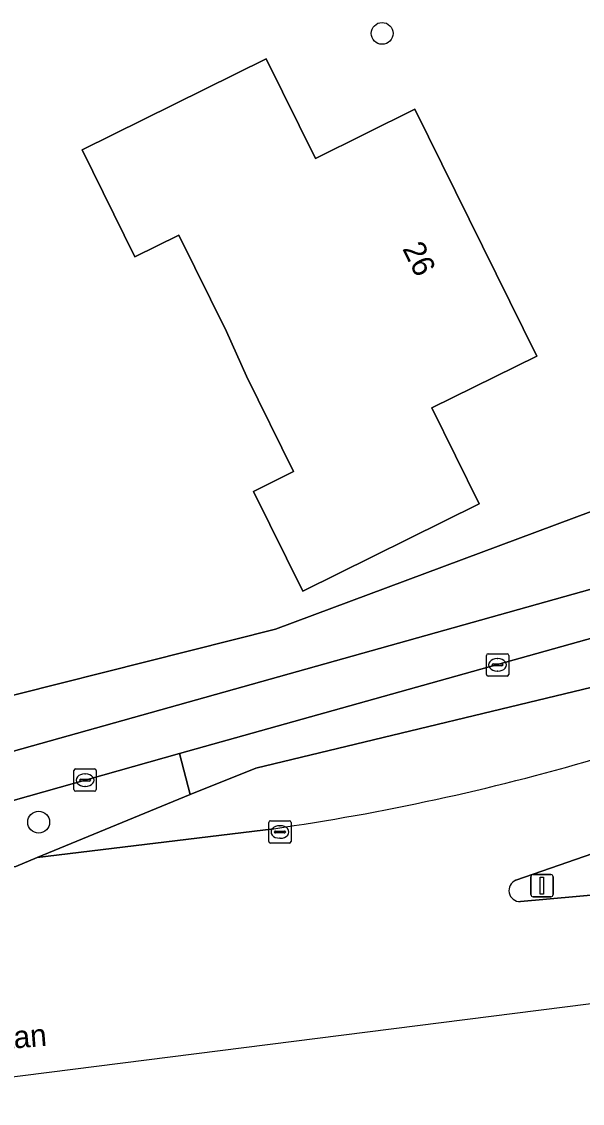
# Model space of a CAD drawing. Extents: x 161087 to 161926, y 382572 to 383873.
# Drawn here: x 161738.69 to 161763.81, y 382571.87 to 382620.31 of the extents above; entities that cross this region are included whole.
import ezdxf

# ---------------------------------------------------------------- set-up
doc = ezdxf.new("R2010")
doc.units = 0
for name, color, linetype in [('IMGEO_Boom', 7, 'Continuous'), ('IMGEO_Erf', 7, 'Continuous'), ('IMGEO_Fietspad_open', 7, 'Continuous'), ('IMGEO_Kolk', 7, 'Continuous'), ('IMGEO_Lichtmast', 7, 'Continuous'), ('IMGEO_Openbare_ruimte_label', 7, 'Continuous'), ('IMGEO_Pand', 7, 'Continuous'), ('IMGEO_Pand_nummerreeks', 7, 'Continuous'), ('IMGEO_Rijbaan_lokaal_gesloten', 7, 'Continuous'), ('IMGEO_Rioolput', 7, 'Continuous'), ('IMGEO_Verkeerseiland_groen', 7, 'Continuous'), ('IMGEO_Verkeerseiland_open', 7, 'Continuous'), ('IMGEO_Voetpad_open', 7, 'Continuous')]:
    doc.layers.add(name, color=color, linetype=linetype)

msp = doc.modelspace()

# ---------------------------------------------------------------- linework, layer by layer
at = {"layer": 'IMGEO_Boom'}
for centre in [(161754.841, 382619.783), (161739.452, 382584.466)]:
    msp.add_circle(centre, 0.489, dxfattribs=at)
at = {"layer": 'IMGEO_Erf'}
msp.add_lwpolyline([(161741.395, 382614.568), (161749.649, 382618.648), (161751.856, 382614.185), (161756.305, 382616.384), (161761.767, 382605.333), (161757.071, 382603.011), (161759.192, 382598.72), (161751.281, 382594.809), (161749.074, 382599.273), (161750.875, 382600.162), (161748.761, 382604.439), (161747.87, 382606.439), (161745.738, 382610.752), (161743.764, 382609.776)], close=True, dxfattribs=at)
msp.add_lwpolyline([(161728.057, 382587.75), (161732.732, 382588.753), (161750.068, 382593.111), (161776.833, 382603.073)], dxfattribs=at)
at = {"layer": 'IMGEO_Fietspad_open'}
for points in [[(161776.981, 382598.483), (161731.713, 382585.795)], [(161727.79, 382582.818), (161733.632, 382584.112), (161735.548, 382584.657), (161745.758, 382587.539), (161767.27, 382593.561), (161777.834, 382596.519), (161780.697, 382597.213), (161780.8, 382597.237), (161780.904, 382597.262)]]:
    msp.add_lwpolyline(points, dxfattribs=at)
at = {"layer": 'IMGEO_Kolk'}
for p, q in [((161741.033, 382585.922), (161741.033, 382586.774)), ((161741.108, 382586.848), (161741.96, 382586.848)), ((161741.521, 382586.628), (161741.546, 382586.628)), ((161742.034, 382586.774), (161742.034, 382585.922)), ((161741.292, 382586.342), (161741.292, 382586.354)), ((161741.73, 382586.305), (161741.332, 382586.305)), ((161741.335, 382586.391), (161741.733, 382586.391)), ((161741.776, 382586.354), (161741.776, 382586.342)), ((161741.96, 382585.848), (161741.108, 382585.848)), ((161741.544, 382586.068), (161741.519, 382586.068)), ((161749.762, 382583.6), (161749.762, 382584.452)), ((161749.837, 382584.526), (161750.689, 382584.526)), ((161750.25, 382584.306), (161750.275, 382584.306)), ((161750.763, 382584.452), (161750.763, 382583.6)), ((161750.021, 382584.02), (161750.021, 382584.032)), ((161750.459, 382583.983), (161750.061, 382583.983)), ((161750.064, 382584.069), (161750.462, 382584.069)), ((161750.273, 382583.746), (161750.248, 382583.746)), ((161750.505, 382584.032), (161750.505, 382584.02)), ((161750.689, 382583.526), (161749.837, 382583.526))]:
    msp.add_line(p, q, dxfattribs=at)
for points in [[(161741.033, 382585.922), (161741.033, 382586.774)], [(161741.108, 382586.848), (161741.96, 382586.848)], [(161742.034, 382586.774), (161742.034, 382585.922)], [(161741.96, 382585.848), (161741.108, 382585.848)], [(161749.762, 382583.6), (161749.762, 382584.452)], [(161749.837, 382584.526), (161750.689, 382584.526)], [(161750.763, 382584.452), (161750.763, 382583.6)], [(161750.689, 382583.526), (161749.837, 382583.526)]]:
    msp.add_lwpolyline(points, dxfattribs=at)
for centre, radius, start, end in [((161741.11, 382586.772), 0.0765, 91.552, 178.448), ((161741.11, 382586.772), 0.0765, 91.552, 178.448), ((161741.958, 382586.772), 0.0765, 1.552, 88.448), ((161741.958, 382586.772), 0.0765, 1.552, 88.448), ((161741.332, 382586.351), 0.0403, 85.8775, 175.7526), ((161741.329, 382586.341), 0.0366, 178.938, 274.7102), ((161741.733, 382586.348), 0.043, 264.8664, 352.4533), ((161741.737, 382586.353), 0.0386, 1.7309, 96.639), ((161741.11, 382585.924), 0.0765, 181.552, 268.448), ((161741.11, 382585.924), 0.0765, 181.552, 268.448), ((161741.958, 382585.924), 0.0765, 271.552, 358.448), ((161741.958, 382585.924), 0.0765, 271.552, 358.448), ((161749.839, 382584.45), 0.0765, 91.552, 178.448), ((161749.839, 382584.45), 0.0765, 91.552, 178.448), ((161750.687, 382584.45), 0.0765, 1.552, 88.448), ((161750.687, 382584.45), 0.0765, 1.552, 88.448), ((161750.061, 382584.029), 0.0403, 85.8775, 175.7526), ((161750.058, 382584.019), 0.0366, 178.938, 274.7102), ((161750.462, 382584.026), 0.043, 264.8664, 352.4533), ((161750.466, 382584.031), 0.0386, 1.7309, 96.639), ((161749.839, 382583.602), 0.0765, 181.552, 268.448), ((161749.839, 382583.602), 0.0765, 181.552, 268.448), ((161750.687, 382583.602), 0.0765, 271.552, 358.448), ((161750.687, 382583.602), 0.0765, 271.552, 358.448)]:
    msp.add_arc(centre, radius, start, end, dxfattribs=at)
for centre, major_axis, ratio, start_param, end_param in [((161741.52, 382586.348), (-0.387, 0.002), 0.722429, 4.712389, 7.853982), ((161741.545, 382586.348), (-0.39, 0.002), 0.717154, 1.570796, 4.712389), ((161750.249, 382584.026), (-0.387, 0.002), 0.722429, 4.712389, 7.853982), ((161750.274, 382584.026), (-0.39, 0.002), 0.717154, 1.570796, 4.712389)]:
    msp.add_ellipse(centre, major_axis=major_axis, ratio=ratio, start_param=start_param, end_param=end_param, dxfattribs=at)
at = {"layer": 'IMGEO_Lichtmast'}
for p, q in [((161761.508, 382581.222), (161761.508, 382582.022)), ((161761.508, 382582.022), (161761.508, 382581.222)), ((161761.608, 382582.122), (161762.398, 382582.122)), ((161762.398, 382582.122), (161761.608, 382582.122)), ((161762.498, 382582.022), (161762.498, 382581.222)), ((161762.498, 382581.222), (161762.498, 382582.022)), ((161762.398, 382581.122), (161761.608, 382581.122)), ((161761.608, 382581.122), (161762.398, 382581.122))]:
    msp.add_line(p, q, dxfattribs=at)
msp.add_lwpolyline([(161761.928, 382581.997), (161762.078, 382581.997), (161762.078, 382581.247), (161761.928, 382581.247), (161761.928, 382581.997)], dxfattribs=at)
for centre, start, end in [((161761.608, 382582.022), 90, 180), ((161761.608, 382582.022), 90, 180), ((161762.398, 382582.022), 0, 90), ((161762.398, 382582.022), 360, 90), ((161761.608, 382581.222), 180, 270), ((161761.608, 382581.222), 180, 270), ((161762.398, 382581.222), 270, 0), ((161762.398, 382581.222), 270, 0)]:
    msp.add_arc(centre, 0.1, start, end, dxfattribs=at)
at = {"layer": 'IMGEO_Pand'}
msp.add_lwpolyline([(161751.281, 382594.809), (161759.192, 382598.72), (161757.071, 382603.011), (161761.767, 382605.333), (161756.305, 382616.384), (161751.856, 382614.185), (161749.649, 382618.648), (161741.395, 382614.568), (161743.764, 382609.776), (161745.738, 382610.752), (161747.87, 382606.439), (161748.761, 382604.439), (161750.875, 382600.162), (161749.074, 382599.273)], close=True, dxfattribs=at)
at = {"layer": 'IMGEO_Rijbaan_lokaal_gesloten'}
for points in [[(161563.602, 382736.77), (161592.087, 382705.487), (161622.627, 382671.947), (161661.586, 382630.771), (161701.238, 382588.176), (161728.827, 382571.874), (161779.525, 382578.285), (161779.123, 382582.55), (161766.2, 382581.371), (161761.033, 382580.909)], [(161777.209, 382591.493), (161766.67, 382591.087), (161749.183, 382586.884), (161746.238, 382585.697), (161739.389, 382582.883), (161749.988, 382584.173)], [(161760.828, 382581.863), (161765.444, 382583.47), (161771.281, 382585.403)], [(161749.988, 382584.173), (161739.389, 382582.883), (161738.423, 382582.476), (161734.508, 382581.982)]]:
    msp.add_lwpolyline(points, dxfattribs=at)
for centre, radius, start, end in [((161735.059, 382687.795), 104.692, 278.19805, 286.26639), ((161735.059, 382687.795), 104.692, 278.19805, 286.26639), ((161761.017, 382581.405), 0.496, 112.3641, 271.8911)]:
    msp.add_arc(centre, radius, start, end, dxfattribs=at)
at = {"layer": 'IMGEO_Rioolput'}
for p, q in [((161759.585, 382592.007), (161760.437, 382592.007)), ((161759.51, 382591.081), (161759.51, 382591.933)), ((161759.769, 382591.501), (161759.769, 382591.513)), ((161759.812, 382591.55), (161760.21, 382591.55)), ((161759.998, 382591.787), (161760.023, 382591.787)), ((161760.253, 382591.513), (161760.253, 382591.501)), ((161760.511, 382591.933), (161760.511, 382591.081)), ((161760.437, 382591.007), (161759.585, 382591.007)), ((161760.207, 382591.464), (161759.809, 382591.464)), ((161760.021, 382591.227), (161759.996, 382591.227))]:
    msp.add_line(p, q, dxfattribs=at)
for points in [[(161759.585, 382592.007), (161760.437, 382592.007)], [(161759.51, 382591.081), (161759.51, 382591.933)], [(161760.511, 382591.933), (161760.511, 382591.081)], [(161760.437, 382591.007), (161759.585, 382591.007)]]:
    msp.add_lwpolyline(points, dxfattribs=at)
for centre, radius, start, end in [((161759.587, 382591.931), 0.0765, 91.552, 178.448), ((161759.587, 382591.931), 0.0765, 91.552, 178.448), ((161760.435, 382591.931), 0.0765, 1.552, 88.448), ((161760.435, 382591.931), 0.0765, 1.552, 88.448), ((161759.809, 382591.51), 0.0403, 85.8775, 175.7526), ((161759.806, 382591.5), 0.0366, 178.938, 274.7102), ((161760.21, 382591.507), 0.043, 264.8664, 352.4533), ((161760.214, 382591.512), 0.0386, 1.7309, 96.639), ((161759.587, 382591.083), 0.0765, 181.552, 268.448), ((161759.587, 382591.083), 0.0765, 181.552, 268.448), ((161760.435, 382591.083), 0.0765, 271.552, 358.448), ((161760.435, 382591.083), 0.0765, 271.552, 358.448)]:
    msp.add_arc(centre, radius, start, end, dxfattribs=at)
for centre, major_axis, ratio, start_param, end_param in [((161759.997, 382591.507), (-0.387, 0.002), 0.722429, 4.712389, 7.853982), ((161760.022, 382591.507), (-0.39, 0.002), 0.717154, 1.570796, 4.712389)]:
    msp.add_ellipse(centre, major_axis=major_axis, ratio=ratio, start_param=start_param, end_param=end_param, dxfattribs=at)
at = {"layer": 'IMGEO_Verkeerseiland_groen'}
for points in [[(161746.238, 382585.697), (161745.758, 382587.539), (161735.548, 382584.657), (161733.632, 382584.112), (161727.79, 382582.818)], [(161734.508, 382581.982), (161738.423, 382582.476), (161739.389, 382582.883), (161746.238, 382585.697)]]:
    msp.add_lwpolyline(points, dxfattribs=at)
at = {"layer": 'IMGEO_Verkeerseiland_open'}
msp.add_lwpolyline([(161761.033, 382580.909), (161766.2, 382581.371), (161765.444, 382583.47), (161760.828, 382581.863)], dxfattribs=at)
msp.add_arc((161761.017, 382581.405), 0.496, 112.3641, 271.8911, dxfattribs=at)
at = {"layer": 'IMGEO_Voetpad_open'}
for points in [[(161776.833, 382603.073), (161750.068, 382593.111), (161732.732, 382588.753), (161728.057, 382587.75)], [(161731.713, 382585.795), (161776.981, 382598.483)], [(161777.834, 382596.519), (161767.27, 382593.561), (161745.758, 382587.539), (161746.238, 382585.697), (161749.183, 382586.884), (161766.67, 382591.087), (161777.209, 382591.493), (161778.241, 382591.541)]]:
    msp.add_lwpolyline(points, dxfattribs=at)

# ---------------------------------------------------------------- texts
at = {"layer": 'IMGEO_Openbare_ruimte_label'}
msp.add_text('P Czn Hooftlaan', height=1, rotation=4.5876, dxfattribs=at).set_placement((161730.14, 382573.672))
at = {"layer": 'IMGEO_Pand_nummerreeks'}
msp.add_text('26', height=1, rotation=296.3011, dxfattribs=at).set_placement((161755.729, 382610.147))

doc.saveas('drawing.dxf')
